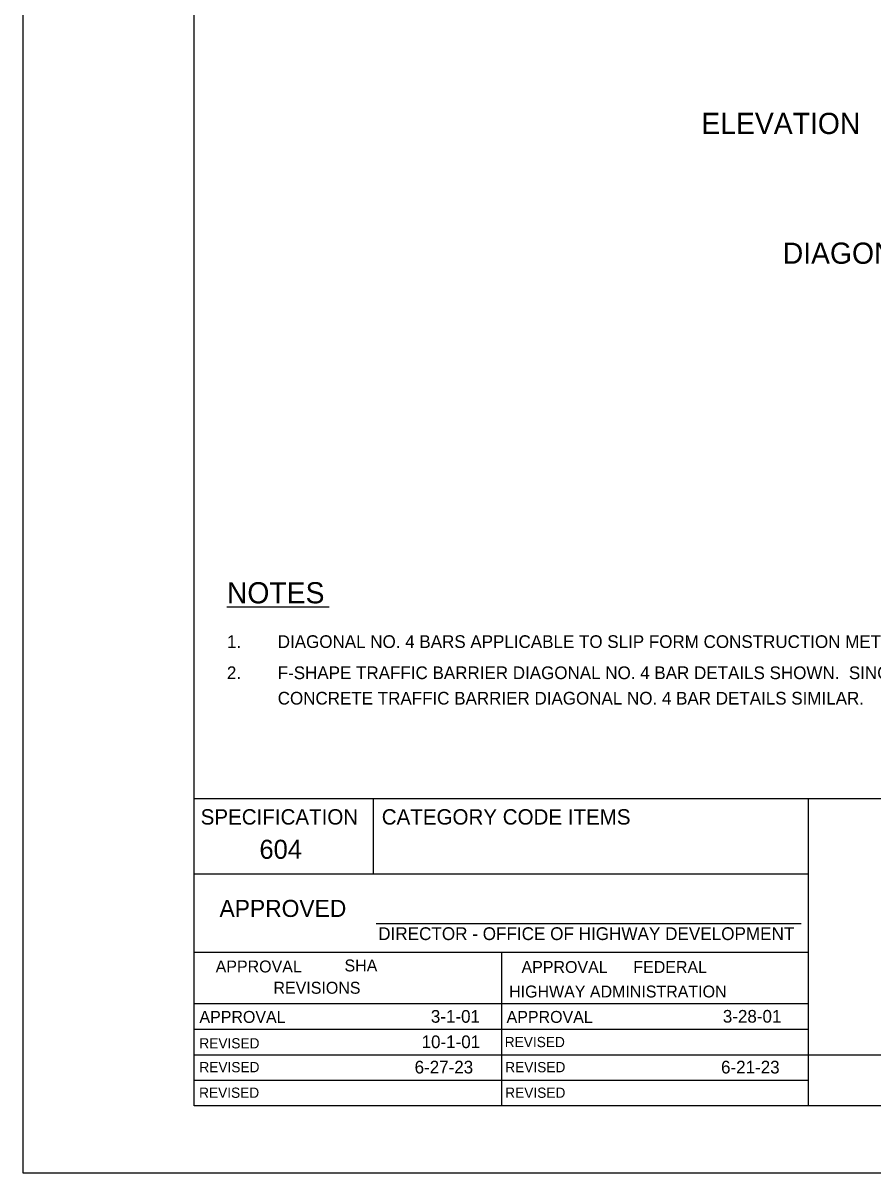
# Model space of a CAD drawing. Extents: x -113.6 to -105.1, y -201.8 to -190.8.
# Drawn here: x -113.61 to -109.6, y -201.78 to -196.35 of the extents above; entities that cross this region are included whole.
import ezdxf

# ---------------------------------------------------------------- set-up
doc = ezdxf.new("R2010")
doc.units = 0
for name, color, linetype in [('BORD-LINE', 7, 'Continuous'), ('Level 12', 7, 'Continuous'), ('Level 13', 7, 'Continuous'), ('TTLB-TEXT', 7, 'Continuous'), ('USER-CLIP', 7, 'Continuous')]:
    doc.layers.add(name, color=color, linetype=linetype)

msp = doc.modelspace()

# ---------------------------------------------------------------- linework, layer by layer
at = {"layer": 'BORD-LINE'}
for p, q in [((-109.9045, -200.01), (-112.8058, -200.01)), ((-111.9596, -200.3647), (-111.9596, -200.01)), ((-109.9045, -201.4608), (-109.9045, -200.01)), ((-105.4316, -200.01), (-109.9045, -200.01)), ((-112.8058, -200.3647), (-109.9045, -200.3647)), ((-111.9466, -200.5998), (-109.9397, -200.5998)), ((-112.8058, -200.7354), (-111.9596, -200.7354)), ((-112.8058, -201.4608), (-112.8058, -200.7354)), ((-112.8058, -200.7354), (-109.9045, -200.7354)), ((-111.3551, -200.7354), (-111.3551, -201.4608)), ((-112.8058, -200.9772), (-109.9045, -200.9772)), ((-112.8058, -201.0981), (-109.9045, -201.0981)), ((-112.8058, -201.219), (-109.9045, -201.219)), ((-109.9045, -201.219), (-105.4316, -201.219)), ((-112.8058, -201.3399), (-109.9045, -201.3399)), ((-111.9596, -201.3399), (-109.9045, -201.3399))]:
    msp.add_line(p, q, dxfattribs=at)
msp.add_lwpolyline([(-112.8058, -191.1077), (-105.4316, -191.1077), (-105.4316, -201.4608), (-112.8058, -201.4608)], close=True, dxfattribs=at)
at = {"layer": 'Level 13'}
msp.add_line((-112.6516, -199.1046), (-112.1692, -199.1046), dxfattribs=at)
at = {"layer": 'USER-CLIP'}
msp.add_lwpolyline([(-105.1147, -190.7777), (-113.6147, -190.7777), (-113.6147, -201.7777), (-105.1147, -201.7777)], close=True, dxfattribs=at)

# ---------------------------------------------------------------- texts
at = {"layer": 'Level 12'}
for s, height, p in [('ELEVATION', 0.10002, (-110.4108, -196.8708)), ('DIAGONAL BAR DETAILS', 0.100016, (-110.0263, -197.4837))]:
    msp.add_text(s, height=height, dxfattribs=at).set_placement(p)
at = {"layer": 'Level 13'}
for s, height, p in [('NOTES', 0.10002, (-112.6516, -199.0875)), ('1.', 0.06001, (-112.6516, -199.2982)), ('DIAGONAL NO. 4 BARS APPLICABLE TO SLIP FORM CONSTRUCTION METHOD ONLY.', 0.06001, (-112.4115, -199.2982)), ('2.', 0.06001, (-112.6517, -199.4453)), ('F-SHAPE TRAFFIC BARRIER DIAGONAL NO. 4 BAR DETAILS SHOWN.  SINGLE SLOPE', 0.06001, (-112.4117, -199.4453)), ('CONCRETE TRAFFIC BARRIER DIAGONAL NO. 4 BAR DETAILS SIMILAR.', 0.06001, (-112.4117, -199.5654)), ('604', 0.09, (-112.498, -200.2939)), ('3-1-01', 0.06, (-111.6884, -201.0681)), ('3-28-01', 0.06, (-110.3094, -201.0677)), ('10-1-01', 0.06, (-111.7321, -201.1881)), ('6-27-23', 0.06, (-111.7652, -201.3077)), ('6-21-23', 0.06, (-110.3178, -201.3077))]:
    msp.add_text(s, height=height, dxfattribs=at).set_placement(p)
at = {"layer": 'TTLB-TEXT'}
for s, height, p in [('SPECIFICATION', 0.07254, (-112.7756, -200.1321)), ('CATEGORY CODE ITEMS ', 0.07254, (-111.9203, -200.1321)), ('APPROVED', 0.0806, (-112.6866, -200.5684)), ('DIRECTOR - OFFICE OF HIGHWAY DEVELOPMENT', 0.0604, (-111.9371, -200.6776)), ('APPROVAL', 0.05642, (-112.7048, -200.8306)), ('SHA', 0.05642, (-112.0962, -200.8259)), ('APPROVAL', 0.05642, (-111.2602, -200.8331)), ('FEDERAL', 0.05642, (-110.7321, -200.833)), ('REVISIONS', 0.05642, (-112.4317, -200.9311)), ('HIGHWAY ADMINISTRATION', 0.05642, (-111.3187, -200.9488)), ('APPROVAL', 0.05642, (-112.7814, -201.0688)), ('APPROVAL', 0.05642, (-111.3307, -201.0688)), ('REVISED', 0.04836, (-112.7817, -201.1893)), ('REVISED', 0.04836, (-111.3394, -201.1834)), ('REVISED', 0.04836, (-112.7817, -201.3019)), ('REVISED', 0.04836, (-111.3371, -201.3019)), ('REVISED', 0.04836, (-112.783, -201.4227)), ('REVISED', 0.04836, (-111.3371, -201.4227))]:
    msp.add_text(s, height=height, dxfattribs=at).set_placement(p)

doc.saveas('drawing.dxf')
